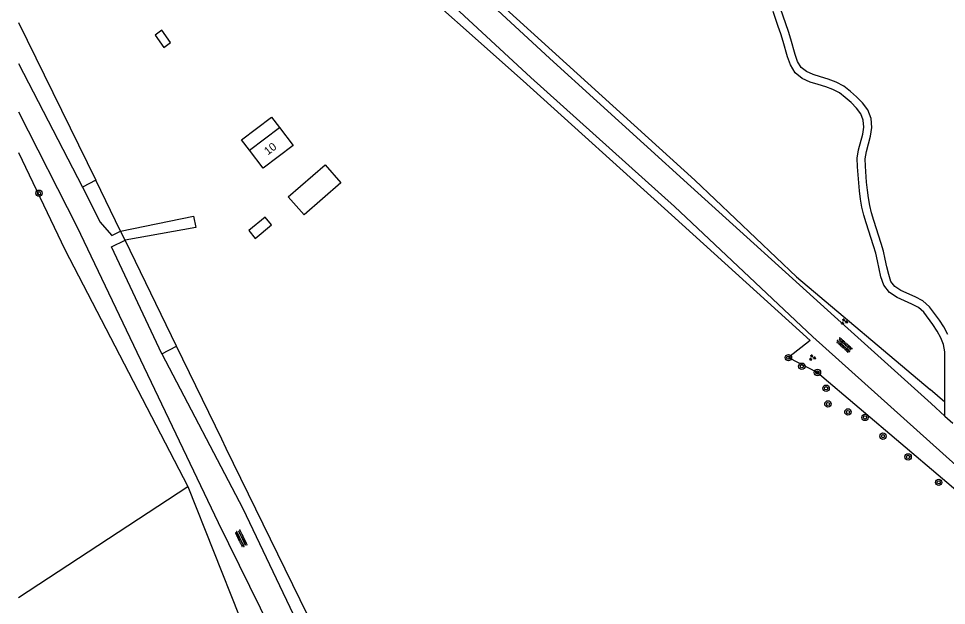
# Model space of a CAD drawing. Extents: x 128999 to 131010, y 395498 to 399007.
# Drawn here: x 129000 to 129116, y 395616.4 to 395689.7 of the extents above; entities that cross this region are included whole.
import ezdxf

# ---------------------------------------------------------------- set-up
doc = ezdxf.new("R2010")
doc.units = 0
for name, color, linetype in [('gg-afsc-draadraster', 7, 'Continuous'), ('gg-afsc-hekwerk', 7, 'Continuous'), ('gg-anno-huisnummerreeks BGT', 7, 'Continuous'), ('gg-bbg-bijgebouw', 7, 'Continuous'), ('gg-bbg-hoofdgebouw', 7, 'Continuous'), ('gg-bbg-luifel en loopbrug', 7, 'Continuous'), ('gg-knt-onverhard', 7, 'Continuous'), ('gt-grn-groengrens', 7, 'Continuous'), ('gt-symb-boom', 7, 'Continuous'), ('gt-symb-groenvak', 7, 'Continuous'), ('gt-symb-overige verharding', 7, 'Continuous')]:
    doc.layers.add(name, color=color, linetype=linetype)

# ---------------------------------------------------------------- blocks, each defined once
blk = doc.blocks.new('gt0-BOOM')
at = {"layer": 'gt-symb-boom'}
for radius in [0.4, 0.2]:
    blk.add_circle((0, 0), radius, dxfattribs=at)
blk = doc.blocks.new('gt0-OVH')
at = {"layer": 'gt-symb-overige verharding'}
for points in [[(-0.97, 0.3), (-0.97, 0.31), (-0.96, 0.32), (-0.97, 0.33), (-0.97, 0.34), (-0.98, 0.35), (-0.99, 0.35), (-1, 0.36), (-1.01, 0.35), (-1.02, 0.35), (-1.03, 0.34), (-1.03, 0.33), (-1.04, 0.32), (-1.03, 0.31), (-1.03, 0.3), (-1.02, 0.29), (-1.01, 0.29), (-1, 0.28), (-0.99, 0.29), (-0.98, 0.29)], [(-0.87, 0.11), (-0.87, 0.12), (-0.86, 0.13), (-0.87, 0.14), (-0.87, 0.15), (-0.88, 0.16), (-0.89, 0.16), (-0.9, 0.16), (-0.91, 0.16), (-0.92, 0.16), (-0.93, 0.15), (-0.93, 0.14), (-0.94, 0.13), (-0.93, 0.12), (-0.93, 0.11), (-0.92, 0.1), (-0.91, 0.09), (-0.9, 0.09), (-0.89, 0.09), (-0.88, 0.1)], [(-0.77, 0.3), (-0.77, 0.31), (-0.76, 0.32), (-0.77, 0.33), (-0.77, 0.34), (-0.78, 0.35), (-0.79, 0.35), (-0.8, 0.36), (-0.81, 0.35), (-0.82, 0.35), (-0.83, 0.34), (-0.83, 0.33), (-0.84, 0.32), (-0.83, 0.31), (-0.83, 0.3), (-0.82, 0.29), (-0.81, 0.29), (-0.8, 0.28), (-0.79, 0.29), (-0.78, 0.29)], [(-0.67, 0.11), (-0.67, 0.12), (-0.66, 0.13), (-0.67, 0.14), (-0.67, 0.15), (-0.68, 0.16), (-0.69, 0.16), (-0.7, 0.16), (-0.71, 0.16), (-0.72, 0.16), (-0.73, 0.15), (-0.73, 0.14), (-0.74, 0.13), (-0.73, 0.12), (-0.73, 0.11), (-0.72, 0.1), (-0.71, 0.09), (-0.7, 0.09), (-0.69, 0.09), (-0.68, 0.1)], [(-0.57, 0.3), (-0.57, 0.31), (-0.56, 0.32), (-0.57, 0.33), (-0.57, 0.34), (-0.58, 0.35), (-0.59, 0.35), (-0.6, 0.36), (-0.61, 0.35), (-0.62, 0.35), (-0.63, 0.34), (-0.63, 0.33), (-0.64, 0.32), (-0.63, 0.31), (-0.63, 0.3), (-0.62, 0.29), (-0.61, 0.29), (-0.6, 0.28), (-0.59, 0.29), (-0.58, 0.29)], [(-0.47, 0.11), (-0.47, 0.12), (-0.46, 0.13), (-0.47, 0.14), (-0.47, 0.15), (-0.48, 0.16), (-0.49, 0.16), (-0.5, 0.16), (-0.51, 0.16), (-0.52, 0.16), (-0.53, 0.15), (-0.53, 0.14), (-0.54, 0.13), (-0.53, 0.12), (-0.53, 0.11), (-0.52, 0.1), (-0.51, 0.09), (-0.5, 0.09), (-0.49, 0.09), (-0.48, 0.1)], [(-0.37, 0.3), (-0.37, 0.31), (-0.36, 0.32), (-0.37, 0.33), (-0.37, 0.34), (-0.38, 0.35), (-0.39, 0.35), (-0.4, 0.36), (-0.41, 0.35), (-0.42, 0.35), (-0.43, 0.34), (-0.43, 0.33), (-0.44, 0.32), (-0.43, 0.31), (-0.43, 0.3), (-0.42, 0.29), (-0.41, 0.29), (-0.4, 0.28), (-0.39, 0.29), (-0.38, 0.29)], [(-0.27, 0.11), (-0.27, 0.12), (-0.26, 0.13), (-0.27, 0.14), (-0.27, 0.15), (-0.28, 0.16), (-0.29, 0.16), (-0.3, 0.16), (-0.31, 0.16), (-0.32, 0.16), (-0.33, 0.15), (-0.33, 0.14), (-0.34, 0.13), (-0.33, 0.12), (-0.33, 0.11), (-0.32, 0.1), (-0.31, 0.09), (-0.3, 0.09), (-0.29, 0.09), (-0.28, 0.1)], [(-0.17, 0.3), (-0.17, 0.31), (-0.16, 0.32), (-0.17, 0.33), (-0.17, 0.34), (-0.18, 0.35), (-0.19, 0.35), (-0.2, 0.36), (-0.21, 0.35), (-0.22, 0.35), (-0.23, 0.34), (-0.23, 0.33), (-0.24, 0.32), (-0.23, 0.31), (-0.23, 0.3), (-0.22, 0.29), (-0.21, 0.29), (-0.2, 0.28), (-0.19, 0.29), (-0.18, 0.29)], [(-0.07, 0.11), (-0.07, 0.12), (-0.06, 0.13), (-0.07, 0.14), (-0.07, 0.15), (-0.08, 0.16), (-0.09, 0.16), (-0.1, 0.16), (-0.11, 0.16), (-0.12, 0.16), (-0.13, 0.15), (-0.13, 0.14), (-0.14, 0.13), (-0.13, 0.12), (-0.13, 0.11), (-0.12, 0.1), (-0.11, 0.09), (-0.1, 0.09), (-0.09, 0.09), (-0.08, 0.1)], [(0.03, 0.3), (0.03, 0.31), (0.04, 0.32), (0.03, 0.33), (0.03, 0.34), (0.02, 0.35), (0.01, 0.35), (0, 0.36), (-0.01, 0.35), (-0.02, 0.35), (-0.03, 0.34), (-0.03, 0.33), (-0.04, 0.32), (-0.03, 0.31), (-0.03, 0.3), (-0.02, 0.29), (-0.01, 0.29), (0, 0.28), (0.01, 0.29), (0.02, 0.29)], [(0.13, 0.11), (0.13, 0.12), (0.14, 0.13), (0.13, 0.14), (0.13, 0.15), (0.12, 0.16), (0.11, 0.16), (0.1, 0.16), (0.09, 0.16), (0.08, 0.16), (0.07, 0.15), (0.07, 0.14), (0.06, 0.13), (0.07, 0.12), (0.07, 0.11), (0.08, 0.1), (0.09, 0.09), (0.1, 0.09), (0.11, 0.09), (0.12, 0.1)], [(0.23, 0.3), (0.23, 0.31), (0.24, 0.32), (0.23, 0.33), (0.23, 0.34), (0.22, 0.35), (0.21, 0.35), (0.2, 0.36), (0.19, 0.35), (0.18, 0.35), (0.17, 0.34), (0.17, 0.33), (0.16, 0.32), (0.17, 0.31), (0.17, 0.3), (0.18, 0.29), (0.19, 0.29), (0.2, 0.28), (0.21, 0.29), (0.22, 0.29)], [(0.33, 0.11), (0.33, 0.12), (0.34, 0.13), (0.33, 0.14), (0.33, 0.15), (0.32, 0.16), (0.31, 0.16), (0.3, 0.16), (0.29, 0.16), (0.28, 0.16), (0.27, 0.15), (0.27, 0.14), (0.26, 0.13), (0.27, 0.12), (0.27, 0.11), (0.28, 0.1), (0.29, 0.09), (0.3, 0.09), (0.31, 0.09), (0.32, 0.1)], [(0.43, 0.3), (0.43, 0.31), (0.44, 0.32), (0.43, 0.33), (0.43, 0.34), (0.42, 0.35), (0.41, 0.35), (0.4, 0.36), (0.39, 0.35), (0.38, 0.35), (0.37, 0.34), (0.37, 0.33), (0.36, 0.32), (0.37, 0.31), (0.37, 0.3), (0.38, 0.29), (0.39, 0.29), (0.4, 0.28), (0.41, 0.29), (0.42, 0.29)], [(0.53, 0.11), (0.53, 0.12), (0.54, 0.13), (0.53, 0.14), (0.53, 0.15), (0.52, 0.16), (0.51, 0.16), (0.5, 0.16), (0.49, 0.16), (0.48, 0.16), (0.47, 0.15), (0.47, 0.14), (0.46, 0.13), (0.47, 0.12), (0.47, 0.11), (0.48, 0.1), (0.49, 0.09), (0.5, 0.09), (0.51, 0.09), (0.52, 0.1)], [(0.63, 0.3), (0.63, 0.31), (0.64, 0.32), (0.63, 0.33), (0.63, 0.34), (0.62, 0.35), (0.61, 0.35), (0.6, 0.36), (0.59, 0.35), (0.58, 0.35), (0.57, 0.34), (0.57, 0.33), (0.56, 0.32), (0.57, 0.31), (0.57, 0.3), (0.58, 0.29), (0.59, 0.29), (0.6, 0.28), (0.61, 0.29), (0.62, 0.29)], [(0.73, 0.11), (0.73, 0.12), (0.74, 0.13), (0.73, 0.14), (0.73, 0.15), (0.72, 0.16), (0.71, 0.16), (0.7, 0.16), (0.69, 0.16), (0.68, 0.16), (0.67, 0.15), (0.67, 0.14), (0.66, 0.13), (0.67, 0.12), (0.67, 0.11), (0.68, 0.1), (0.69, 0.09), (0.7, 0.09), (0.71, 0.09), (0.72, 0.1)], [(0.83, 0.3), (0.83, 0.31), (0.84, 0.32), (0.83, 0.33), (0.83, 0.34), (0.82, 0.35), (0.81, 0.35), (0.8, 0.36), (0.79, 0.35), (0.78, 0.35), (0.77, 0.34), (0.77, 0.33), (0.76, 0.32), (0.77, 0.31), (0.77, 0.3), (0.78, 0.29), (0.79, 0.29), (0.8, 0.28), (0.81, 0.29), (0.82, 0.29)], [(0.93, 0.11), (0.93, 0.12), (0.94, 0.13), (0.93, 0.14), (0.93, 0.15), (0.92, 0.16), (0.91, 0.16), (0.9, 0.16), (0.89, 0.16), (0.88, 0.16), (0.87, 0.15), (0.87, 0.14), (0.86, 0.13), (0.87, 0.12), (0.87, 0.11), (0.88, 0.1), (0.89, 0.09), (0.9, 0.09), (0.91, 0.09), (0.92, 0.1)], [(1.03, 0.3), (1.03, 0.31), (1.04, 0.32), (1.03, 0.33), (1.03, 0.34), (1.02, 0.35), (1.01, 0.35), (1, 0.36), (0.99, 0.35), (0.98, 0.35), (0.97, 0.34), (0.97, 0.33), (0.96, 0.32), (0.97, 0.31), (0.97, 0.3), (0.98, 0.29), (0.99, 0.29), (1, 0.28), (1.01, 0.29), (1.02, 0.29)], [(-0.97, -0.14), (-0.97, -0.13), (-0.96, -0.12), (-0.97, -0.11), (-0.97, -0.1), (-0.98, -0.09), (-0.99, -0.09), (-1, -0.08), (-1.01, -0.09), (-1.02, -0.09), (-1.03, -0.1), (-1.03, -0.11), (-1.04, -0.12), (-1.03, -0.13), (-1.03, -0.14), (-1.02, -0.15), (-1.01, -0.15), (-1, -0.16), (-0.99, -0.15), (-0.98, -0.15)], [(-0.87, -0.33), (-0.87, -0.32), (-0.86, -0.31), (-0.87, -0.3), (-0.87, -0.29), (-0.88, -0.28), (-0.89, -0.28), (-0.9, -0.28), (-0.91, -0.28), (-0.92, -0.28), (-0.93, -0.29), (-0.93, -0.3), (-0.94, -0.31), (-0.93, -0.32), (-0.93, -0.33), (-0.92, -0.34), (-0.91, -0.35), (-0.9, -0.35), (-0.89, -0.35), (-0.88, -0.34)], [(-0.77, -0.14), (-0.77, -0.13), (-0.76, -0.12), (-0.77, -0.11), (-0.77, -0.1), (-0.78, -0.09), (-0.79, -0.09), (-0.8, -0.08), (-0.81, -0.09), (-0.82, -0.09), (-0.83, -0.1), (-0.83, -0.11), (-0.84, -0.12), (-0.83, -0.13), (-0.83, -0.14), (-0.82, -0.15), (-0.81, -0.15), (-0.8, -0.16), (-0.79, -0.15), (-0.78, -0.15)], [(-0.67, -0.33), (-0.67, -0.32), (-0.66, -0.31), (-0.67, -0.3), (-0.67, -0.29), (-0.68, -0.28), (-0.69, -0.28), (-0.7, -0.28), (-0.71, -0.28), (-0.72, -0.28), (-0.73, -0.29), (-0.73, -0.3), (-0.74, -0.31), (-0.73, -0.32), (-0.73, -0.33), (-0.72, -0.34), (-0.71, -0.35), (-0.7, -0.35), (-0.69, -0.35), (-0.68, -0.34)], [(-0.57, -0.14), (-0.57, -0.13), (-0.56, -0.12), (-0.57, -0.11), (-0.57, -0.1), (-0.58, -0.09), (-0.59, -0.09), (-0.6, -0.08), (-0.61, -0.09), (-0.62, -0.09), (-0.63, -0.1), (-0.63, -0.11), (-0.64, -0.12), (-0.63, -0.13), (-0.63, -0.14), (-0.62, -0.15), (-0.61, -0.15), (-0.6, -0.16), (-0.59, -0.15), (-0.58, -0.15)], [(-0.47, -0.33), (-0.47, -0.32), (-0.46, -0.31), (-0.47, -0.3), (-0.47, -0.29), (-0.48, -0.28), (-0.49, -0.28), (-0.5, -0.28), (-0.51, -0.28), (-0.52, -0.28), (-0.53, -0.29), (-0.53, -0.3), (-0.54, -0.31), (-0.53, -0.32), (-0.53, -0.33), (-0.52, -0.34), (-0.51, -0.35), (-0.5, -0.35), (-0.49, -0.35), (-0.48, -0.34)], [(-0.37, -0.14), (-0.37, -0.13), (-0.36, -0.12), (-0.37, -0.11), (-0.37, -0.1), (-0.38, -0.09), (-0.39, -0.09), (-0.4, -0.08), (-0.41, -0.09), (-0.42, -0.09), (-0.43, -0.1), (-0.43, -0.11), (-0.44, -0.12), (-0.43, -0.13), (-0.43, -0.14), (-0.42, -0.15), (-0.41, -0.15), (-0.4, -0.16), (-0.39, -0.15), (-0.38, -0.15)], [(-0.27, -0.33), (-0.27, -0.32), (-0.26, -0.31), (-0.27, -0.3), (-0.27, -0.29), (-0.28, -0.28), (-0.29, -0.28), (-0.3, -0.28), (-0.31, -0.28), (-0.32, -0.28), (-0.33, -0.29), (-0.33, -0.3), (-0.34, -0.31), (-0.33, -0.32), (-0.33, -0.33), (-0.32, -0.34), (-0.31, -0.35), (-0.3, -0.35), (-0.29, -0.35), (-0.28, -0.34)], [(-0.17, -0.14), (-0.17, -0.13), (-0.16, -0.12), (-0.17, -0.11), (-0.17, -0.1), (-0.18, -0.09), (-0.19, -0.09), (-0.2, -0.08), (-0.21, -0.09), (-0.22, -0.09), (-0.23, -0.1), (-0.23, -0.11), (-0.24, -0.12), (-0.23, -0.13), (-0.23, -0.14), (-0.22, -0.15), (-0.21, -0.15), (-0.2, -0.16), (-0.19, -0.15), (-0.18, -0.15)], [(-0.07, -0.33), (-0.07, -0.32), (-0.06, -0.31), (-0.07, -0.3), (-0.07, -0.29), (-0.08, -0.28), (-0.09, -0.28), (-0.1, -0.28), (-0.11, -0.28), (-0.12, -0.28), (-0.13, -0.29), (-0.13, -0.3), (-0.14, -0.31), (-0.13, -0.32), (-0.13, -0.33), (-0.12, -0.34), (-0.11, -0.35), (-0.1, -0.35), (-0.09, -0.35), (-0.08, -0.34)], [(0.03, -0.14), (0.03, -0.13), (0.04, -0.12), (0.03, -0.11), (0.03, -0.1), (0.02, -0.09), (0.01, -0.09), (0, -0.08), (-0.01, -0.09), (-0.02, -0.09), (-0.03, -0.1), (-0.03, -0.11), (-0.04, -0.12), (-0.03, -0.13), (-0.03, -0.14), (-0.02, -0.15), (-0.01, -0.15), (0, -0.16), (0.01, -0.15), (0.02, -0.15)], [(0.13, -0.33), (0.13, -0.32), (0.14, -0.31), (0.13, -0.3), (0.13, -0.29), (0.12, -0.28), (0.11, -0.28), (0.1, -0.28), (0.09, -0.28), (0.08, -0.28), (0.07, -0.29), (0.07, -0.3), (0.06, -0.31), (0.07, -0.32), (0.07, -0.33), (0.08, -0.34), (0.09, -0.35), (0.1, -0.35), (0.11, -0.35), (0.12, -0.34)], [(0.23, -0.14), (0.23, -0.13), (0.24, -0.12), (0.23, -0.11), (0.23, -0.1), (0.22, -0.09), (0.21, -0.09), (0.2, -0.08), (0.19, -0.09), (0.18, -0.09), (0.17, -0.1), (0.17, -0.11), (0.16, -0.12), (0.17, -0.13), (0.17, -0.14), (0.18, -0.15), (0.19, -0.15), (0.2, -0.16), (0.21, -0.15), (0.22, -0.15)], [(0.33, -0.33), (0.33, -0.32), (0.34, -0.31), (0.33, -0.3), (0.33, -0.29), (0.32, -0.28), (0.31, -0.28), (0.3, -0.28), (0.29, -0.28), (0.28, -0.28), (0.27, -0.29), (0.27, -0.3), (0.26, -0.31), (0.27, -0.32), (0.27, -0.33), (0.28, -0.34), (0.29, -0.35), (0.3, -0.35), (0.31, -0.35), (0.32, -0.34)], [(0.43, -0.14), (0.43, -0.13), (0.44, -0.12), (0.43, -0.11), (0.43, -0.1), (0.42, -0.09), (0.41, -0.09), (0.4, -0.08), (0.39, -0.09), (0.38, -0.09), (0.37, -0.1), (0.37, -0.11), (0.36, -0.12), (0.37, -0.13), (0.37, -0.14), (0.38, -0.15), (0.39, -0.15), (0.4, -0.16), (0.41, -0.15), (0.42, -0.15)], [(0.53, -0.33), (0.53, -0.32), (0.54, -0.31), (0.53, -0.3), (0.53, -0.29), (0.52, -0.28), (0.51, -0.28), (0.5, -0.28), (0.49, -0.28), (0.48, -0.28), (0.47, -0.29), (0.47, -0.3), (0.46, -0.31), (0.47, -0.32), (0.47, -0.33), (0.48, -0.34), (0.49, -0.35), (0.5, -0.35), (0.51, -0.35), (0.52, -0.34)], [(0.63, -0.14), (0.63, -0.13), (0.64, -0.12), (0.63, -0.11), (0.63, -0.1), (0.62, -0.09), (0.61, -0.09), (0.6, -0.08), (0.59, -0.09), (0.58, -0.09), (0.57, -0.1), (0.57, -0.11), (0.56, -0.12), (0.57, -0.13), (0.57, -0.14), (0.58, -0.15), (0.59, -0.15), (0.6, -0.16), (0.61, -0.15), (0.62, -0.15)], [(0.73, -0.33), (0.73, -0.32), (0.74, -0.31), (0.73, -0.3), (0.73, -0.29), (0.72, -0.28), (0.71, -0.28), (0.7, -0.28), (0.69, -0.28), (0.68, -0.28), (0.67, -0.29), (0.67, -0.3), (0.66, -0.31), (0.67, -0.32), (0.67, -0.33), (0.68, -0.34), (0.69, -0.35), (0.7, -0.35), (0.71, -0.35), (0.72, -0.34)], [(0.83, -0.14), (0.83, -0.13), (0.84, -0.12), (0.83, -0.11), (0.83, -0.1), (0.82, -0.09), (0.81, -0.09), (0.8, -0.08), (0.79, -0.09), (0.78, -0.09), (0.77, -0.1), (0.77, -0.11), (0.76, -0.12), (0.77, -0.13), (0.77, -0.14), (0.78, -0.15), (0.79, -0.15), (0.8, -0.16), (0.81, -0.15), (0.82, -0.15)], [(0.93, -0.33), (0.93, -0.32), (0.94, -0.31), (0.93, -0.3), (0.93, -0.29), (0.92, -0.28), (0.91, -0.28), (0.9, -0.28), (0.89, -0.28), (0.88, -0.28), (0.87, -0.29), (0.87, -0.3), (0.86, -0.31), (0.87, -0.32), (0.87, -0.33), (0.88, -0.34), (0.89, -0.35), (0.9, -0.35), (0.91, -0.35), (0.92, -0.34)], [(1.03, -0.14), (1.03, -0.13), (1.04, -0.12), (1.03, -0.11), (1.03, -0.1), (1.02, -0.09), (1.01, -0.09), (1, -0.08), (0.99, -0.09), (0.98, -0.09), (0.97, -0.1), (0.97, -0.11), (0.96, -0.12), (0.97, -0.13), (0.97, -0.14), (0.98, -0.15), (0.99, -0.15), (1, -0.16), (1.01, -0.15), (1.02, -0.15)]]:
    blk.add_lwpolyline(points, close=True, dxfattribs=at)
blk = doc.blocks.new('gt0-GRVAK')
at = {"layer": 'gt-symb-groenvak'}
for p, q in [((-0.11, 0.19), (-0.23, 0.24)), ((-0.18, 0.15), (0.09, 0.15)), ((-0.09, 0.21), (-0.16, 0.32)), ((-0.05, 0.21), (-0.05, 0.39)), ((0, 0.21), (0.06, 0.32)), ((0.01, 0.19), (0.13, 0.24)), ((0.26, -0.05), (0.2, 0.06)), ((0.31, -0.05), (0.31, 0.13)), ((0.35, -0.05), (0.41, 0.06)), ((-0.24, -0.23), (-0.36, -0.18)), ((-0.32, -0.26), (-0.05, -0.26)), ((-0.23, -0.21), (-0.29, -0.1)), ((-0.18, -0.2), (-0.18, -0.02)), ((-0.14, -0.21), (-0.07, -0.1)), ((-0.12, -0.23), (0, -0.18)), ((0.24, -0.07), (0.12, -0.02)), ((0.17, -0.11), (0.44, -0.11)), ((0.37, -0.07), (0.49, -0.02))]:
    blk.add_line(p, q, dxfattribs=at)

msp = doc.modelspace()

# ---------------------------------------------------------------- linework, layer by layer
at = {"layer": 'gg-afsc-draadraster'}
for p, q in [((129025.39, 395637.15), (129019.76, 395648.78)), ((129115.78, 395641.78), (129113.93, 395643.35)), ((129036.11, 395615.18), (129025.94, 395635.96)), ((129021.17, 395631.24), (129027.56, 395615.06))]:
    msp.add_line(p, q, dxfattribs=at)
for points in [[(129000, 395746.24), (129031.49, 395717.65), (129084.54, 395669.53), (129097.25, 395657.45), (129113.93, 395643.35)], [(129063.05, 395681.93), (129081.62, 395665.17), (129098.95, 395649.49), (129096.22, 395647.34)], [(129000, 395672.96), (129005.77, 395660.86), (129021.17, 395631.24)]]:
    msp.add_lwpolyline(points, dxfattribs=at)
at = {"layer": 'gg-afsc-hekwerk'}
for p, q in [((129000, 395689.22), (129009.65, 395669.52)), ((129012.75, 395663.16), (129009.65, 395669.52)), ((129013.31, 395662.01), (129012.75, 395663.16)), ((129019.76, 395648.78), (129013.31, 395662.01)), ((129025.94, 395635.96), (129025.39, 395637.15))]:
    msp.add_line(p, q, dxfattribs=at)
msp.add_lwpolyline([(129000, 395738.67), (129035.29, 395706.94), (129046.29, 395696.91), (129063.05, 395681.93)], dxfattribs=at)
at = {"layer": 'gg-bbg-bijgebouw'}
for points in [[(129017.92, 395688.26), (129017.07, 395687.66), (129018.15, 395686.11), (129019.01, 395686.71), (129017.92, 395688.26)], [(129028.77, 395663.23), (129029.57, 395662.25), (129031.61, 395663.94), (129030.81, 395664.91), (129028.77, 395663.23)]]:
    msp.add_lwpolyline(points, dxfattribs=at)
at = {"layer": 'gg-bbg-hoofdgebouw'}
msp.add_line((129028.86, 395673.28), (129032.61, 395676.12), dxfattribs=at)
msp.add_lwpolyline([(129032.61, 395676.12), (129034.32, 395673.86), (129030.56, 395671.02), (129028.86, 395673.28)], dxfattribs=at)
at = {"layer": 'gg-bbg-luifel en loopbrug'}
for points in [[(129028.86, 395673.28), (129027.88, 395674.58), (129031.63, 395677.41), (129032.61, 395676.12)], [(129035.68, 395665.19), (129033.71, 395667.45), (129038.32, 395671.45), (129040.28, 395669.19), (129035.68, 395665.19)]]:
    msp.add_lwpolyline(points, dxfattribs=at)
at = {"layer": 'gg-knt-onverhard'}
for p, q in [((129000, 395684.09), (129007.98, 395668.65)), ((129114.06, 395641.59), (129115.78, 395640.04)), ((129115.78, 395640.04), (129115.78, 395641.78)), ((129115.78, 395640.04), (129116.78, 395639.14))]:
    msp.add_line(p, q, dxfattribs=at)
for points in [[(129000, 395745.31), (129029.17, 395718.67), (129050.05, 395699.85), (129066.39, 395684.71), (129084.01, 395668.71), (129101.96, 395652.5), (129114.06, 395641.59)], [(129000, 395739.97), (129017.34, 395724.73), (129030.24, 395713.19), (129047.37, 395697.8), (129064.02, 395682.34), (129081.97, 395666.22), (129099.27, 395649.94), (129123.64, 395628.08), (129146.6, 395607.66), (129169.7, 395587.28), (129199.22, 395559.73), (129231.57, 395530.15), (129252.63, 395511.74), (129266.59, 395500)], [(129115.78, 395641.78), (129115.78, 395647.11), (129115.76, 395648.07), (129115.59, 395648.96), (129115.25, 395649.82), (129114.8, 395650.65), (129114.26, 395651.46), (129113.13, 395653.02), (129112.46, 395653.6), (129111.64, 395654.04), (129109.8, 395654.86), (129108.85, 395655.47), (129108.13, 395656.39), (129107.79, 395657.45), (129107.56, 395658.45), (129107.36, 395659.43), (129107.13, 395660.38), (129106.85, 395661.32), (129105.94, 395664.18), (129105.65, 395665.16), (129105.41, 395666.15), (129105.22, 395667.16), (129105.09, 395668.18), (129105, 395669.19), (129104.87, 395671.2), (129104.82, 395672.25), (129104.98, 395673.31), (129105.5, 395675.25), (129105.64, 395676.15), (129105.57, 395677.01), (129105.25, 395677.81), (129104.72, 395678.54), (129104.05, 395679.21), (129103.32, 395679.84), (129102.59, 395680.43), (129101.78, 395680.86), (129100.88, 395681.18), (129099.93, 395681.46), (129098.94, 395681.78), (129097.95, 395682.23), (129097.05, 395682.95), (129096.46, 395683.92), (129096.1, 395684.93), (129095.58, 395686.87), (129095.27, 395687.8), (129094.94, 395688.74), (129094.3, 395690.62)], [(129116.16, 395650.24), (129115.65, 395651.17), (129115.09, 395652.03), (129113.87, 395653.7), (129113.03, 395654.43), (129112.08, 395654.94), (129110.28, 395655.74), (129109.54, 395656.22), (129109.03, 395656.87), (129108.76, 395657.72), (129108.54, 395658.67), (129108.33, 395659.65), (129108.1, 395660.64), (129107.8, 395661.61), (129106.89, 395664.47), (129106.62, 395665.42), (129106.39, 395666.36), (129106.21, 395667.32), (129106.09, 395668.29), (129105.99, 395669.27), (129105.86, 395671.25), (129105.82, 395672.2), (129105.96, 395673.11), (129106.48, 395675.04), (129106.65, 395676.11), (129106.56, 395677.24), (129106.13, 395678.3), (129105.48, 395679.19), (129104.74, 395679.94), (129103.96, 395680.61), (129103.14, 395681.28), (129102.18, 395681.78), (129101.19, 395682.13), (129100.23, 395682.42), (129099.31, 395682.72), (129098.48, 395683.09), (129097.81, 395683.62), (129097.37, 395684.36), (129097.05, 395685.23), (129096.53, 395687.15), (129096.22, 395688.12), (129095.88, 395689.07), (129095.23, 395690.97)], [(129000, 395678.05), (129007.28, 395663.75), (129024.96, 395626.72), (129045.91, 395584.16), (129060.33, 395554.49), (129070.67, 395531.86), (129085.94, 395500)], [(129007.98, 395668.65), (129009.5, 395665.69), (129010.16, 395664.3), (129011.64, 395662.62), (129012.75, 395663.16)], [(129012.75, 395663.16), (129021.88, 395665.02), (129022.17, 395663.6), (129013.31, 395662.01)], [(129017.91, 395647.81), (129011.62, 395661.19), (129013.31, 395662.01)], [(129017.91, 395647.81), (129028.03, 395628.5), (129048.54, 395585.45), (129063.08, 395555.49), (129074.31, 395531.74), (129090.61, 395500)]]:
    msp.add_lwpolyline(points, dxfattribs=at)
at = {"layer": 'gt-grn-groengrens'}
for p, q in [((129009.65, 395669.52), (129007.98, 395668.65)), ((129017.91, 395647.81), (129019.76, 395648.78)), ((129000, 395617.35), (129021.17, 395631.24))]:
    msp.add_line(p, q, dxfattribs=at)
msp.add_lwpolyline([(129096.22, 395647.34), (129099.85, 395645.48), (129120.68, 395627.83), (129144.63, 395605.41), (129165.81, 395588.44), (129168.79, 395586.25)], dxfattribs=at)

# ---------------------------------------------------------------- block references
at = {"layer": 'gt-symb-boom'}
for p in [(129002.56, 395667.89), (129096.22, 395647.34), (129097.9, 395646.26), (129099.85, 395645.48), (129100.93, 395643.51), (129101.16, 395641.55), (129103.66, 395640.55), (129105.79, 395639.86), (129108.04, 395637.52), (129111.18, 395634.93), (129115, 395631.75)]:
    msp.add_blockref('gt0-BOOM', p, dxfattribs=at)
at = {"layer": 'gt-symb-groenvak'}
for p in [(129103.19, 395651.83), (129099.2, 395647.33)]:
    msp.add_blockref('gt0-GRVAK', p, dxfattribs=at)
at = {"layer": 'gt-symb-overige verharding'}
for p, rotation in [((129103.19, 395648.89), -41.59548170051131), ((129027.82, 395624.72), -64.02428534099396)]:
    msp.add_blockref('gt0-OVH', p, dxfattribs=dict(at, rotation=rotation))

# ---------------------------------------------------------------- texts
at = {"layer": 'gg-anno-huisnummerreeks BGT'}
msp.add_text('10', height=1, rotation=37.2, dxfattribs=at).set_placement((129031.16, 395672.61))

doc.saveas('drawing.dxf')
